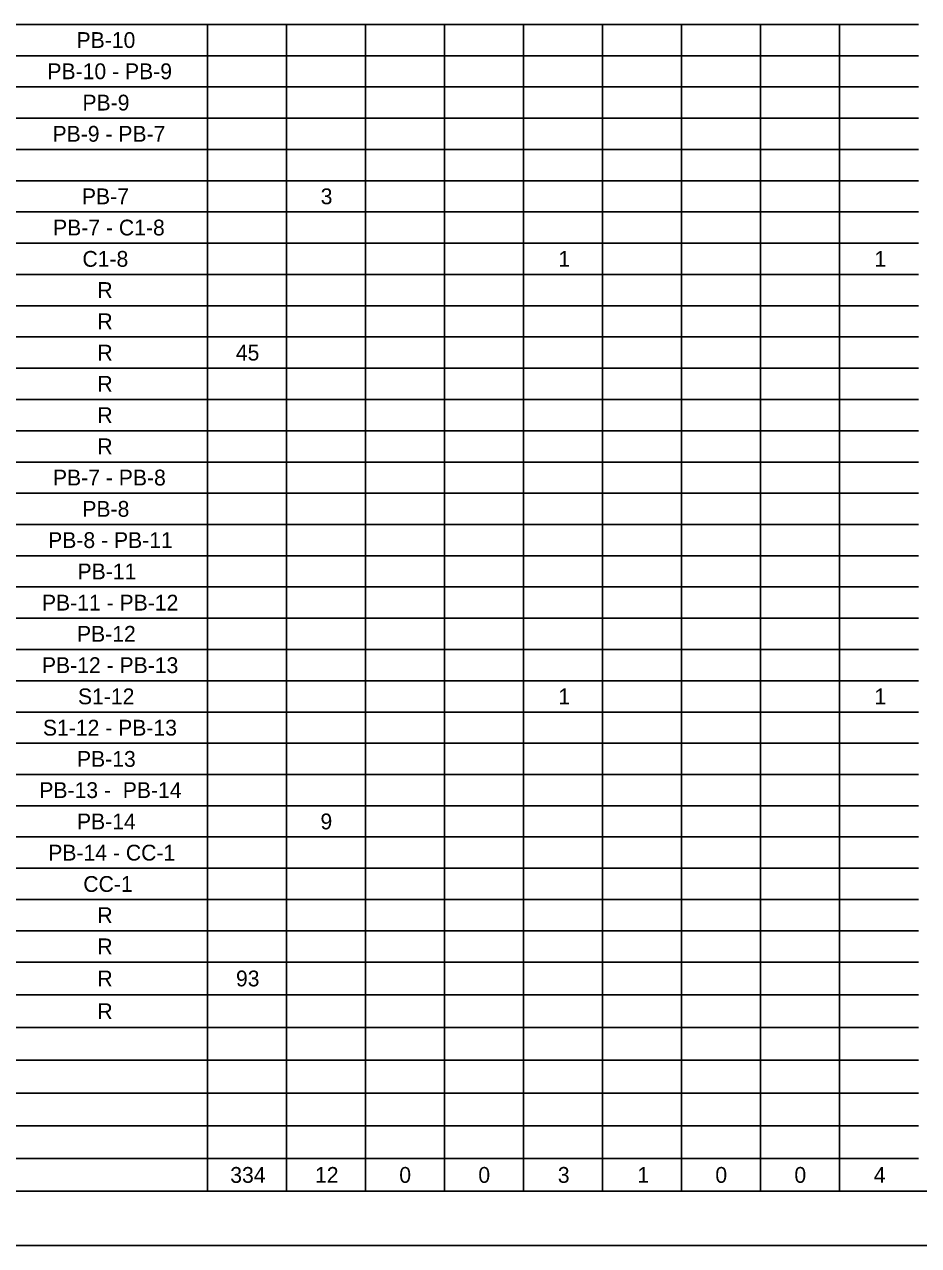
# Model space of a CAD drawing. Extents: x 0 to 34, y 0 to 22.
# Drawn here: x 8.63 to 16.82, y 0 to 11.19 of the extents above; entities that cross this region are included whole.
import ezdxf

# ---------------------------------------------------------------- set-up
doc = ezdxf.new("R2010")
doc.units = 0
for name, color, linetype in [('Default', 7, 'Continuous'), ('SH_Border', 7, 'Continuous'), ('SH_Cut_Line', 7, 'Continuous')]:
    doc.layers.add(name, color=color, linetype=linetype)

msp = doc.modelspace()

# ---------------------------------------------------------------- linework, layer by layer
at = {"layer": 'Default'}
for p, q in [((5.433, 11.19), (13.203, 11.19)), ((10.308, 11.19), (10.308, 10.903)), ((11.032, 11.19), (11.032, 10.903)), ((11.756, 11.19), (11.756, 10.903)), ((12.479, 11.19), (12.479, 10.903)), ((13.203, 11.19), (13.927, 11.19)), ((13.203, 11.19), (13.203, 10.903)), ((13.927, 11.19), (14.651, 11.19)), ((13.927, 11.19), (13.927, 10.903)), ((14.651, 11.19), (15.374, 11.19)), ((14.651, 11.19), (14.651, 10.903)), ((15.374, 11.19), (16.822, 11.19)), ((15.374, 11.19), (15.374, 10.903)), ((16.098, 11.19), (16.098, 10.903)), ((5.433, 10.903), (13.203, 10.903)), ((10.308, 10.903), (10.308, 10.617)), ((11.032, 10.903), (11.032, 10.617)), ((11.756, 10.903), (11.756, 10.617)), ((12.479, 10.903), (12.479, 10.617)), ((13.203, 10.903), (13.927, 10.903)), ((13.203, 10.903), (13.203, 10.617)), ((13.927, 10.903), (14.651, 10.903)), ((13.927, 10.903), (13.927, 10.617)), ((14.651, 10.903), (15.374, 10.903)), ((14.651, 10.903), (14.651, 10.617)), ((15.374, 10.903), (16.822, 10.903)), ((15.374, 10.903), (15.374, 10.617)), ((16.098, 10.903), (16.098, 10.617)), ((5.433, 10.617), (13.203, 10.617)), ((10.308, 10.617), (10.308, 10.331)), ((11.032, 10.617), (11.032, 10.331)), ((11.756, 10.617), (11.756, 10.331)), ((12.479, 10.617), (12.479, 10.331)), ((13.203, 10.617), (13.927, 10.617)), ((13.203, 10.617), (13.203, 10.331)), ((13.927, 10.617), (14.651, 10.617)), ((13.927, 10.617), (13.927, 10.331)), ((14.651, 10.617), (15.374, 10.617)), ((14.651, 10.617), (14.651, 10.331)), ((15.374, 10.617), (16.822, 10.617)), ((15.374, 10.617), (15.374, 10.331)), ((16.098, 10.617), (16.098, 10.331)), ((5.433, 10.331), (13.203, 10.331)), ((10.308, 10.331), (10.308, 10.044)), ((11.032, 10.331), (11.032, 10.044)), ((11.756, 10.331), (11.756, 10.044)), ((12.479, 10.331), (12.479, 10.044)), ((13.203, 10.331), (13.927, 10.331)), ((13.203, 10.331), (13.203, 10.044)), ((13.927, 10.331), (14.651, 10.331)), ((13.927, 10.331), (13.927, 10.044)), ((14.651, 10.331), (15.374, 10.331)), ((14.651, 10.331), (14.651, 10.044)), ((15.374, 10.331), (16.822, 10.331)), ((15.374, 10.331), (15.374, 10.044)), ((16.098, 10.331), (16.098, 10.044)), ((5.433, 10.044), (13.203, 10.044)), ((10.308, 10.044), (10.308, 9.758)), ((11.032, 10.044), (11.032, 9.758)), ((11.756, 10.044), (11.756, 9.758)), ((12.479, 10.044), (12.479, 9.758)), ((13.203, 10.044), (13.927, 10.044)), ((13.203, 10.044), (13.203, 9.758)), ((13.927, 10.044), (14.651, 10.044)), ((13.927, 10.044), (13.927, 9.758)), ((14.651, 10.044), (15.374, 10.044)), ((14.651, 10.044), (14.651, 9.758)), ((15.374, 10.044), (16.822, 10.044)), ((15.374, 10.044), (15.374, 9.758)), ((16.098, 10.044), (16.098, 9.758)), ((5.433, 9.758), (13.203, 9.758)), ((10.308, 9.758), (10.308, 9.471)), ((11.032, 9.758), (11.032, 9.471)), ((11.756, 9.758), (11.756, 9.471)), ((12.479, 9.758), (12.479, 9.471)), ((13.203, 9.758), (13.927, 9.758)), ((13.203, 9.758), (13.203, 9.471)), ((13.927, 9.758), (14.651, 9.758)), ((13.927, 9.758), (13.927, 9.471)), ((14.651, 9.758), (15.374, 9.758)), ((14.651, 9.758), (14.651, 9.471)), ((15.374, 9.758), (16.822, 9.758)), ((15.374, 9.758), (15.374, 9.471)), ((16.098, 9.758), (16.098, 9.471)), ((5.433, 9.471), (13.203, 9.471)), ((10.308, 9.471), (10.308, 9.185)), ((11.032, 9.471), (11.032, 9.185)), ((11.756, 9.471), (11.756, 9.185)), ((12.479, 9.471), (12.479, 9.185)), ((13.203, 9.471), (13.927, 9.471)), ((13.203, 9.471), (13.203, 9.185)), ((13.927, 9.471), (14.651, 9.471)), ((13.927, 9.471), (13.927, 9.185)), ((14.651, 9.471), (15.374, 9.471)), ((14.651, 9.471), (14.651, 9.185)), ((15.374, 9.471), (16.822, 9.471)), ((15.374, 9.471), (15.374, 9.185)), ((16.098, 9.471), (16.098, 9.185)), ((5.433, 9.185), (13.203, 9.185)), ((10.308, 9.185), (10.308, 8.899)), ((11.032, 9.185), (11.032, 8.899)), ((11.756, 9.185), (11.756, 8.899)), ((12.479, 9.185), (12.479, 8.899)), ((13.203, 9.185), (13.927, 9.185)), ((13.203, 9.185), (13.203, 8.899)), ((13.927, 9.185), (14.651, 9.185)), ((13.927, 9.185), (13.927, 8.899)), ((14.651, 9.185), (15.374, 9.185)), ((14.651, 9.185), (14.651, 8.899)), ((15.374, 9.185), (16.822, 9.185)), ((15.374, 9.185), (15.374, 8.899)), ((16.098, 9.185), (16.098, 8.899)), ((5.433, 8.899), (13.203, 8.899)), ((10.308, 8.899), (10.308, 8.612)), ((11.032, 8.899), (11.032, 8.612)), ((11.756, 8.899), (11.756, 8.612)), ((12.479, 8.899), (12.479, 8.612)), ((13.203, 8.899), (13.927, 8.899)), ((13.203, 8.899), (13.203, 8.612)), ((13.927, 8.899), (14.651, 8.899)), ((13.927, 8.899), (13.927, 8.612)), ((14.651, 8.899), (15.374, 8.899)), ((14.651, 8.899), (14.651, 8.612)), ((15.374, 8.899), (16.822, 8.899)), ((15.374, 8.899), (15.374, 8.612)), ((16.098, 8.899), (16.098, 8.612)), ((5.433, 8.612), (13.203, 8.612)), ((10.308, 8.612), (10.308, 8.326)), ((11.032, 8.612), (11.032, 8.326)), ((11.756, 8.612), (11.756, 8.326)), ((12.479, 8.612), (12.479, 8.326)), ((13.203, 8.612), (13.927, 8.612)), ((13.203, 8.612), (13.203, 8.326)), ((13.927, 8.612), (14.651, 8.612)), ((13.927, 8.612), (13.927, 8.326)), ((14.651, 8.612), (15.374, 8.612)), ((14.651, 8.612), (14.651, 8.326)), ((15.374, 8.612), (16.822, 8.612)), ((15.374, 8.612), (15.374, 8.326)), ((16.098, 8.612), (16.098, 8.326)), ((5.433, 8.326), (13.203, 8.326)), ((10.308, 8.326), (10.308, 8.039)), ((11.032, 8.326), (11.032, 8.039)), ((11.756, 8.326), (11.756, 8.039)), ((12.479, 8.326), (12.479, 8.039)), ((13.203, 8.326), (13.927, 8.326)), ((13.203, 8.326), (13.203, 8.039)), ((13.927, 8.326), (14.651, 8.326)), ((13.927, 8.326), (13.927, 8.039)), ((14.651, 8.326), (15.374, 8.326)), ((14.651, 8.326), (14.651, 8.039)), ((15.374, 8.326), (16.822, 8.326)), ((15.374, 8.326), (15.374, 8.039)), ((16.098, 8.326), (16.098, 8.039)), ((5.433, 8.039), (13.203, 8.039)), ((10.308, 8.039), (10.308, 7.753)), ((11.032, 8.039), (11.032, 7.753)), ((11.756, 8.039), (11.756, 7.753)), ((12.479, 8.039), (12.479, 7.753)), ((13.203, 8.039), (13.927, 8.039)), ((13.203, 8.039), (13.203, 7.753)), ((13.927, 8.039), (14.651, 8.039)), ((13.927, 8.039), (13.927, 7.753)), ((14.651, 8.039), (15.374, 8.039)), ((14.651, 8.039), (14.651, 7.753)), ((15.374, 8.039), (16.822, 8.039)), ((15.374, 8.039), (15.374, 7.753)), ((16.098, 8.039), (16.098, 7.753)), ((5.433, 7.753), (13.203, 7.753)), ((10.308, 7.753), (10.308, 7.467)), ((11.032, 7.753), (11.032, 7.467)), ((11.756, 7.753), (11.756, 7.467)), ((12.479, 7.753), (12.479, 7.467)), ((13.203, 7.753), (13.927, 7.753)), ((13.203, 7.753), (13.203, 7.467)), ((13.927, 7.753), (14.651, 7.753)), ((13.927, 7.753), (13.927, 7.467)), ((14.651, 7.753), (15.374, 7.753)), ((14.651, 7.753), (14.651, 7.467)), ((15.374, 7.753), (16.822, 7.753)), ((15.374, 7.753), (15.374, 7.467)), ((16.098, 7.753), (16.098, 7.467)), ((5.433, 7.467), (13.203, 7.467)), ((10.308, 7.467), (10.308, 7.18)), ((11.032, 7.467), (11.032, 7.18)), ((11.756, 7.467), (11.756, 7.18)), ((12.479, 7.467), (12.479, 7.18)), ((13.203, 7.467), (13.927, 7.467)), ((13.203, 7.467), (13.203, 7.18)), ((13.927, 7.467), (14.651, 7.467)), ((13.927, 7.467), (13.927, 7.18)), ((14.651, 7.467), (15.374, 7.467)), ((14.651, 7.467), (14.651, 7.18)), ((15.374, 7.467), (16.822, 7.467)), ((15.374, 7.467), (15.374, 7.18)), ((16.098, 7.467), (16.098, 7.18)), ((5.433, 7.18), (13.203, 7.18)), ((10.308, 7.18), (10.308, 6.894)), ((11.032, 7.18), (11.032, 6.894)), ((11.756, 7.18), (11.756, 6.894)), ((12.479, 7.18), (12.479, 6.894)), ((13.203, 7.18), (13.927, 7.18)), ((13.203, 7.18), (13.203, 6.894)), ((13.927, 7.18), (14.651, 7.18)), ((13.927, 7.18), (13.927, 6.894)), ((14.651, 7.18), (15.374, 7.18)), ((14.651, 7.18), (14.651, 6.894)), ((15.374, 7.18), (16.822, 7.18)), ((15.374, 7.18), (15.374, 6.894)), ((16.098, 7.18), (16.098, 6.894)), ((5.433, 6.894), (13.203, 6.894)), ((10.308, 6.894), (10.308, 6.607)), ((11.032, 6.894), (11.032, 6.607)), ((11.756, 6.894), (11.756, 6.607)), ((12.479, 6.894), (12.479, 6.607)), ((13.203, 6.894), (13.927, 6.894)), ((13.203, 6.894), (13.203, 6.607)), ((13.927, 6.894), (14.651, 6.894)), ((13.927, 6.894), (13.927, 6.607)), ((14.651, 6.894), (15.374, 6.894)), ((14.651, 6.894), (14.651, 6.607)), ((15.374, 6.894), (16.822, 6.894)), ((15.374, 6.894), (15.374, 6.607)), ((16.098, 6.894), (16.098, 6.607)), ((5.433, 6.607), (13.203, 6.607)), ((10.308, 6.607), (10.308, 6.321)), ((11.032, 6.607), (11.032, 6.321)), ((11.756, 6.607), (11.756, 6.321)), ((12.479, 6.607), (12.479, 6.321)), ((13.203, 6.607), (13.927, 6.607)), ((13.203, 6.607), (13.203, 6.321)), ((13.927, 6.607), (14.651, 6.607)), ((13.927, 6.607), (13.927, 6.321)), ((14.651, 6.607), (15.374, 6.607)), ((14.651, 6.607), (14.651, 6.321)), ((15.374, 6.607), (16.822, 6.607)), ((15.374, 6.607), (15.374, 6.321)), ((16.098, 6.607), (16.098, 6.321)), ((5.433, 6.321), (13.203, 6.321)), ((10.308, 6.321), (10.308, 6.035)), ((11.032, 6.321), (11.032, 6.035)), ((11.756, 6.321), (11.756, 6.035)), ((12.479, 6.321), (12.479, 6.035)), ((13.203, 6.321), (13.927, 6.321)), ((13.203, 6.321), (13.203, 6.035)), ((13.927, 6.321), (14.651, 6.321)), ((13.927, 6.321), (13.927, 6.035)), ((14.651, 6.321), (15.374, 6.321)), ((14.651, 6.321), (14.651, 6.035)), ((15.374, 6.321), (16.822, 6.321)), ((15.374, 6.321), (15.374, 6.035)), ((16.098, 6.321), (16.098, 6.035)), ((5.433, 6.035), (13.203, 6.035)), ((10.308, 6.035), (10.308, 5.748)), ((11.032, 6.035), (11.032, 5.748)), ((11.756, 6.035), (11.756, 5.748)), ((12.479, 6.035), (12.479, 5.748)), ((13.203, 6.035), (13.927, 6.035)), ((13.203, 6.035), (13.203, 5.748)), ((13.927, 6.035), (14.651, 6.035)), ((13.927, 6.035), (13.927, 5.748)), ((14.651, 6.035), (15.374, 6.035)), ((14.651, 6.035), (14.651, 5.748)), ((15.374, 6.035), (16.822, 6.035)), ((15.374, 6.035), (15.374, 5.748)), ((16.098, 6.035), (16.098, 5.748)), ((5.433, 5.748), (13.203, 5.748)), ((10.308, 5.748), (10.308, 5.462)), ((11.032, 5.748), (11.032, 5.462)), ((11.756, 5.748), (11.756, 5.462)), ((12.479, 5.748), (12.479, 5.462)), ((13.203, 5.748), (13.927, 5.748)), ((13.203, 5.748), (13.203, 5.462)), ((13.927, 5.748), (14.651, 5.748)), ((13.927, 5.748), (13.927, 5.462)), ((14.651, 5.748), (15.374, 5.748)), ((14.651, 5.748), (14.651, 5.462)), ((15.374, 5.748), (16.822, 5.748)), ((15.374, 5.748), (15.374, 5.462)), ((16.098, 5.748), (16.098, 5.462)), ((5.433, 5.462), (13.203, 5.462)), ((10.308, 5.462), (10.308, 5.175)), ((11.032, 5.462), (11.032, 5.175)), ((11.756, 5.462), (11.756, 5.175)), ((12.479, 5.462), (12.479, 5.175)), ((13.203, 5.462), (13.927, 5.462)), ((13.203, 5.462), (13.203, 5.175)), ((13.927, 5.462), (14.651, 5.462)), ((13.927, 5.462), (13.927, 5.175)), ((14.651, 5.462), (15.374, 5.462)), ((14.651, 5.462), (14.651, 5.175)), ((15.374, 5.462), (16.822, 5.462)), ((15.374, 5.462), (15.374, 5.175)), ((16.098, 5.462), (16.098, 5.175)), ((5.433, 5.175), (13.203, 5.175)), ((10.308, 5.175), (10.308, 4.603)), ((11.032, 5.175), (11.032, 4.603)), ((11.756, 5.175), (11.756, 4.603)), ((12.479, 5.175), (12.479, 4.603)), ((13.203, 5.175), (13.927, 5.175)), ((13.203, 5.175), (13.203, 4.603)), ((13.927, 5.175), (14.651, 5.175)), ((13.927, 5.175), (13.927, 4.603)), ((14.651, 5.175), (15.374, 5.175)), ((14.651, 5.175), (14.651, 4.603)), ((15.374, 5.175), (16.822, 5.175)), ((15.374, 5.175), (15.374, 4.603)), ((16.098, 5.175), (16.098, 4.603)), ((5.433, 4.889), (13.203, 4.889)), ((13.203, 4.889), (13.927, 4.889)), ((13.927, 4.889), (14.651, 4.889)), ((14.651, 4.889), (15.374, 4.889)), ((15.374, 4.889), (16.822, 4.889)), ((5.433, 4.603), (13.203, 4.603)), ((10.308, 4.603), (10.308, 4.316)), ((11.032, 4.603), (11.032, 4.316)), ((11.756, 4.603), (11.756, 4.316)), ((12.479, 4.603), (12.479, 4.316)), ((13.203, 4.603), (13.927, 4.603)), ((13.203, 4.603), (13.203, 4.316)), ((13.927, 4.603), (14.651, 4.603)), ((13.927, 4.603), (13.927, 4.316)), ((14.651, 4.603), (15.374, 4.603)), ((14.651, 4.603), (14.651, 4.316)), ((15.374, 4.603), (16.822, 4.603)), ((15.374, 4.603), (15.374, 4.316)), ((16.098, 4.603), (16.098, 4.316)), ((5.433, 4.316), (13.203, 4.316)), ((10.308, 4.316), (10.308, 4.03)), ((11.032, 4.316), (11.032, 4.03)), ((11.756, 4.316), (11.756, 4.03)), ((12.479, 4.316), (12.479, 4.03)), ((13.203, 4.316), (13.927, 4.316)), ((13.203, 4.316), (13.203, 4.03)), ((13.927, 4.316), (14.651, 4.316)), ((13.927, 4.316), (13.927, 4.03)), ((14.651, 4.316), (15.374, 4.316)), ((14.651, 4.316), (14.651, 4.03)), ((15.374, 4.316), (16.822, 4.316)), ((15.374, 4.316), (15.374, 4.03)), ((16.098, 4.316), (16.098, 4.03)), ((5.433, 4.03), (13.203, 4.03)), ((10.308, 4.03), (10.308, 3.744)), ((11.032, 4.03), (11.032, 3.744)), ((11.756, 4.03), (11.756, 3.744)), ((12.479, 4.03), (12.479, 3.744)), ((13.203, 4.03), (13.927, 4.03)), ((13.203, 4.03), (13.203, 3.744)), ((13.927, 4.03), (14.651, 4.03)), ((13.927, 4.03), (13.927, 3.744)), ((14.651, 4.03), (15.374, 4.03)), ((14.651, 4.03), (14.651, 3.744)), ((15.374, 4.03), (16.822, 4.03)), ((15.374, 4.03), (15.374, 3.744)), ((16.098, 4.03), (16.098, 3.744)), ((5.433, 3.744), (13.203, 3.744)), ((10.308, 3.744), (10.308, 3.171)), ((11.032, 3.744), (11.032, 3.171)), ((11.756, 3.744), (11.756, 3.171)), ((12.479, 3.744), (12.479, 3.171)), ((13.203, 3.744), (13.927, 3.744)), ((13.203, 3.744), (13.203, 3.171)), ((13.927, 3.744), (14.651, 3.744)), ((13.927, 3.744), (13.927, 3.171)), ((14.651, 3.744), (15.374, 3.744)), ((14.651, 3.744), (14.651, 3.171)), ((15.374, 3.744), (16.822, 3.744)), ((15.374, 3.744), (15.374, 3.171)), ((16.098, 3.744), (16.098, 3.171)), ((5.433, 3.457), (13.203, 3.457)), ((13.203, 3.457), (13.927, 3.457)), ((13.927, 3.457), (14.651, 3.457)), ((14.651, 3.457), (15.374, 3.457)), ((15.374, 3.457), (16.822, 3.457)), ((5.433, 3.171), (13.203, 3.171)), ((10.308, 3.171), (10.308, 2.884)), ((11.032, 3.171), (11.032, 2.884)), ((11.756, 3.171), (11.756, 2.884)), ((12.479, 3.171), (12.479, 2.884)), ((13.203, 3.171), (13.927, 3.171)), ((13.203, 3.171), (13.203, 2.884)), ((13.927, 3.171), (14.651, 3.171)), ((13.927, 3.171), (13.927, 2.884)), ((14.651, 3.171), (15.374, 3.171)), ((14.651, 3.171), (14.651, 2.884)), ((15.374, 3.171), (16.822, 3.171)), ((15.374, 3.171), (15.374, 2.884)), ((16.098, 3.171), (16.098, 2.884)), ((5.433, 2.884), (13.203, 2.884)), ((10.308, 2.884), (10.308, 2.598)), ((11.032, 2.884), (11.032, 2.598)), ((11.756, 2.884), (11.756, 2.598)), ((12.479, 2.884), (12.479, 2.598)), ((13.203, 2.884), (13.927, 2.884)), ((13.203, 2.884), (13.203, 2.598)), ((13.927, 2.884), (14.651, 2.884)), ((13.927, 2.884), (13.927, 2.598)), ((14.651, 2.884), (15.374, 2.884)), ((14.651, 2.884), (14.651, 2.598)), ((15.374, 2.884), (16.822, 2.884)), ((15.374, 2.884), (15.374, 2.598)), ((16.098, 2.884), (16.098, 2.598)), ((5.433, 2.598), (13.203, 2.598)), ((10.308, 2.598), (10.308, 2.298)), ((11.032, 2.598), (11.032, 2.298)), ((11.756, 2.598), (11.756, 2.298)), ((12.479, 2.598), (12.479, 2.298)), ((13.203, 2.598), (13.927, 2.598)), ((13.203, 2.598), (13.203, 2.298)), ((13.927, 2.598), (14.651, 2.598)), ((13.927, 2.598), (13.927, 2.298)), ((14.651, 2.598), (15.374, 2.598)), ((14.651, 2.598), (14.651, 2.298)), ((15.374, 2.598), (16.822, 2.598)), ((15.374, 2.598), (15.374, 2.298)), ((16.098, 2.598), (16.098, 2.298)), ((5.433, 2.298), (13.203, 2.298)), ((10.308, 2.298), (10.308, 1.398)), ((11.032, 2.298), (11.032, 1.398)), ((11.756, 2.298), (11.756, 1.398)), ((12.479, 2.298), (12.479, 1.398)), ((13.203, 2.298), (13.927, 2.298)), ((13.203, 2.298), (13.203, 1.398)), ((13.927, 2.298), (14.651, 2.298)), ((13.927, 2.298), (13.927, 1.398)), ((14.651, 2.298), (15.374, 2.298)), ((14.651, 2.298), (14.651, 1.398)), ((15.374, 2.298), (16.822, 2.298)), ((15.374, 2.298), (15.374, 1.398)), ((16.098, 2.298), (16.098, 1.398)), ((5.433, 1.998), (13.203, 1.998)), ((13.203, 1.998), (13.927, 1.998)), ((13.927, 1.998), (14.651, 1.998)), ((14.651, 1.998), (15.374, 1.998)), ((15.374, 1.998), (16.822, 1.998)), ((5.433, 1.698), (13.203, 1.698)), ((13.203, 1.698), (13.927, 1.698)), ((13.927, 1.698), (14.651, 1.698)), ((14.651, 1.698), (15.374, 1.698)), ((15.374, 1.698), (16.822, 1.698)), ((5.433, 1.398), (13.203, 1.398)), ((10.308, 1.398), (10.308, 0.798)), ((11.032, 1.398), (11.032, 0.798)), ((11.756, 1.398), (11.756, 0.798)), ((12.479, 1.398), (12.479, 0.798)), ((13.203, 1.398), (13.927, 1.398)), ((13.203, 1.398), (13.203, 0.798)), ((13.927, 1.398), (14.651, 1.398)), ((13.927, 1.398), (13.927, 0.798)), ((14.651, 1.398), (15.374, 1.398)), ((14.651, 1.398), (14.651, 0.798)), ((15.374, 1.398), (16.822, 1.398)), ((15.374, 1.398), (15.374, 0.798)), ((16.098, 1.398), (16.098, 0.798)), ((5.433, 1.098), (13.203, 1.098)), ((13.203, 1.098), (13.927, 1.098)), ((13.927, 1.098), (14.651, 1.098)), ((14.651, 1.098), (15.374, 1.098)), ((15.374, 1.098), (16.822, 1.098)), ((5.433, 0.798), (13.203, 0.798)), ((10.308, 0.798), (10.308, 0.498)), ((11.032, 0.798), (11.032, 0.498)), ((11.756, 0.798), (11.756, 0.498)), ((12.479, 0.798), (12.479, 0.498)), ((13.203, 0.798), (13.927, 0.798)), ((13.203, 0.798), (13.203, 0.498)), ((13.927, 0.798), (14.651, 0.798)), ((13.927, 0.798), (13.927, 0.498)), ((14.651, 0.798), (15.374, 0.798)), ((14.651, 0.798), (14.651, 0.498)), ((15.374, 0.798), (16.822, 0.798)), ((15.374, 0.798), (15.374, 0.498)), ((16.098, 0.798), (16.098, 0.498)), ((5.433, 0.498), (13.203, 0.498)), ((13.203, 0.498), (13.927, 0.498)), ((13.927, 0.498), (14.651, 0.498)), ((14.651, 0.498), (15.374, 0.498)), ((15.374, 0.498), (16.822, 0.498))]:
    msp.add_line(p, q, dxfattribs=at)
at = {"layer": 'SH_Border'}
msp.add_lwpolyline([(1.5, 21.5), (33.5, 21.5), (33.5, 0.5), (1.5, 0.5)], close=True, dxfattribs=at)
at = {"layer": 'SH_Cut_Line'}
msp.add_lwpolyline([(0, 0), (34, 0), (34, 22), (0, 22)], close=True, dxfattribs=at)

# ---------------------------------------------------------------- texts
at = {"layer": 'Default'}
for s, height, p in [('PB-10', 0.1449, (9.11, 10.974)), ('PB-10 - PB-9', 0.1449, (8.843, 10.688)), ('PB-9', 0.1449, (9.164, 10.401)), ('PB-9 - PB-7', 0.1449, (8.89, 10.115)), ('PB-7', 0.1449, (9.159, 9.542)), ('3', 0.145, (11.346, 9.542)), ('PB-7 - C1-8', 0.1449, (8.895, 9.256)), ('C1-8', 0.1449, (9.164, 8.969)), ('1', 0.145, (13.523, 8.969)), ('1', 0.145, (16.418, 8.969)), ('R', 0.145, (9.301, 8.683)), ('R', 0.145, (9.301, 8.397)), ('R', 0.145, (9.301, 8.11)), ('45', 0.1449, (10.569, 8.11)), ('R', 0.145, (9.301, 7.824)), ('R', 0.145, (9.301, 7.537)), ('R', 0.145, (9.301, 7.251)), ('PB-7 - PB-8', 0.1449, (8.894, 6.965)), ('PB-8', 0.1449, (9.163, 6.678)), ('PB-8 - PB-11', 0.1449, (8.85, 6.392)), ('PB-11', 0.1449, (9.119, 6.105)), ('PB-11 - PB-12', 0.1449, (8.793, 5.819)), ('PB-12', 0.1449, (9.114, 5.533)), ('PB-12 - PB-13', 0.1449, (8.793, 5.246)), ('S1-12', 0.1449, (9.123, 4.96)), ('1', 0.145, (13.523, 4.96)), ('1', 0.145, (16.418, 4.96)), ('S1-12 - PB-13', 0.1449, (8.802, 4.673)), ('PB-13', 0.1449, (9.114, 4.387)), ('PB-13 -  PB-14', 0.1449, (8.769, 4.101)), ('PB-14', 0.1449, (9.114, 3.814)), ('9', 0.145, (11.344, 3.814)), ('PB-14 - CC-1', 0.1449, (8.851, 3.528)), ('CC-1', 0.1449, (9.172, 3.241)), ('R', 0.145, (9.301, 2.955)), ('R', 0.145, (9.301, 2.669)), ('R', 0.145, (9.301, 2.375)), ('93', 0.1449, (10.57, 2.375)), ('R', 0.145, (9.301, 2.075)), ('334', 0.1449, (10.518, 0.575)), ('12', 0.1449, (11.294, 0.575)), ('0', 0.145, (12.066, 0.575)), ('0', 0.145, (12.79, 0.575)), ('3', 0.145, (13.518, 0.575)), ('1', 0.145, (14.247, 0.575)), ('0', 0.145, (14.961, 0.575)), ('0', 0.145, (15.685, 0.575)), ('4', 0.145, (16.412, 0.575))]:
    msp.add_text(s, height=height, dxfattribs=at).set_placement(p)

doc.saveas('drawing.dxf')
